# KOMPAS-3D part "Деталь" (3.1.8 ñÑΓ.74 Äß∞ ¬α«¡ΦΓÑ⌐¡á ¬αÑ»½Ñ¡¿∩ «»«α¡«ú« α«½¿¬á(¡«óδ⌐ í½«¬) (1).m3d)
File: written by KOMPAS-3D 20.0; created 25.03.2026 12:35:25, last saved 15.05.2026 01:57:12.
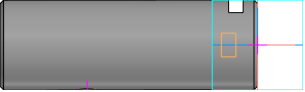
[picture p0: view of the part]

Document properties: Автор: TMK; Полное имя файла: E:\test_kompas\all_v18\3.1.8 дет.74 Ось кронштейна крепления опорного ролика(новый блок) (1).m3d; Организация: TMK

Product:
- Part/product: Деталь
    Масса: 2.04624
  - Body: Тело 1

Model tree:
1. Эскиз:1
2. Элемент выдавливания:1
     Расстояние 2 = 142
3. Фаска:1
     Угол = 45; Длина 1 = 2; Длина 2 = 2
4. Эскиз:2
5. Отверстие:2  (with: Элемент выдавливания:1)
     Глубина выреза = 99.5; Диаметр отверстия = 11.4448; Угол конуса дна = 118; Диаметр цековки = 23; Глубина цековки = 12
6. G 1/4  (with: Отверстие:2)
     Длина резьбы = 20; Шаг резьбы = 1.337; Номинальный диаметр резьбы = 13.157
7. Фаска:2
     Угол = 45; Длина 1 = 1.6; Длина 2 = 1.6
8. Смещенная плоскость:2
     Расстояние = 25
9. Эскиз:4
10. Отверстие:3
     Глубина выреза = 30.5; Диаметр отверстия = 11.5; Угол конуса дна = 118; Расстояние 2 = -94
11. Смещенная плоскость:3
     Расстояние = 25
12. Эскиз:5
13. Элемент выдавливания:3
     Расстояние 2 = 50

Expressions: cil2_6357-81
